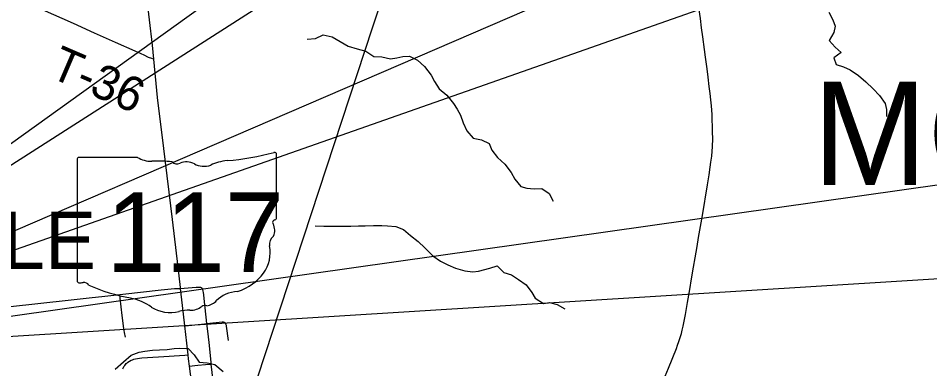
# Model space of a CAD drawing. Extents: x 0 to 34, y -5.4 to 22.
# Drawn here: x 5.887 to 7.394, y 17.496 to 18.075 of the extents above; entities that cross this region are included whole.
import ezdxf

# ---------------------------------------------------------------- set-up
doc = ezdxf.new("R2010")
doc.units = 0
for name, color, linetype in [('GM_X_City_Street', 7, 'Continuous'), ('GM_X_Corporation_Text', 7, 'Continuous'), ('GM_X_County_Road', 7, 'Continuous'), ('GM_X_Minor_River', 7, 'Continuous'), ('GM_X_Rail_Line', 7, 'Continuous'), ('GM_X_State_Location', 7, 'Continuous'), ('GM_X_State_Route', 7, 'Continuous'), ('GM_X_State_Shield', 7, 'Continuous'), ('GM_X_Township_Road', 7, 'Continuous'), ('GM_X_Township_Road_Text', 7, 'Continuous'), ('GM_X_Township_Text', 7, 'Continuous'), ('SH_Data', 7, 'Continuous')]:
    doc.layers.add(name, color=color, linetype=linetype)

msp = doc.modelspace()

# ---------------------------------------------------------------- linework, layer by layer
at = {"layer": 'GM_X_City_Street'}
for points in [[(6.1547, 17.6286), (6.1809, 17.6309), (6.184, 17.631), (6.1865, 17.6309), (6.188, 17.6308), (6.1893, 17.6304), (6.1901, 17.63), (6.1911, 17.6291)], [(6.2188, 17.3787), (6.2188, 17.3805), (6.2184, 17.3908), (6.218, 17.3978), (6.2177, 17.4025), (6.2162, 17.4177), (6.2132, 17.4434), (6.2093, 17.4763), (6.2061, 17.5038), (6.2057, 17.5073), (6.2023, 17.5396), (6.2002, 17.5585), (6.1989, 17.5707), (6.1943, 17.6123), (6.1937, 17.6185), (6.1932, 17.6219), (6.1927, 17.6245), (6.1921, 17.6269), (6.1911, 17.6291)], [(6.0645, 17.5485), (6.0626, 17.5561), (6.0614, 17.5624), (6.0587, 17.5839), (6.0554, 17.6128), (6.0547, 17.619)], [(6.1618, 17.5671), (6.1632, 17.5672), (6.1947, 17.5703), (6.1989, 17.5707), (6.2242, 17.5734), (6.2256, 17.5734), (6.2273, 17.5732), (6.2281, 17.5728), (6.2287, 17.5724), (6.2293, 17.5717), (6.2298, 17.5706), (6.2302, 17.5695), (6.2306, 17.5682), (6.2309, 17.5667), (6.234, 17.543)], [(6.0598, 17.4958), (6.0607, 17.498), (6.0618, 17.4997), (6.0631, 17.5017), (6.0643, 17.5033), (6.0654, 17.5047), (6.0669, 17.5059), (6.0684, 17.5072), (6.0709, 17.5089), (6.0738, 17.5102), (6.0758, 17.511), (6.0783, 17.512), (6.081, 17.5126), (6.084, 17.5133), (6.0874, 17.5137), (6.0913, 17.514), (6.1187, 17.5157), (6.1625, 17.5186), (6.1673, 17.5189)], [(6.1695, 17.5007), (6.1838, 17.502), (6.1965, 17.503), (6.2061, 17.5038)]]:
    msp.add_lwpolyline(points, dxfattribs=at)
at = {"layer": 'GM_X_County_Road'}
msp.add_lwpolyline([(6.956, 17.4841), (6.9615, 17.4973), (6.9747, 17.5295), (6.9768, 17.5351), (6.9791, 17.5412), (6.9811, 17.5476), (6.9831, 17.5543), (6.9846, 17.56), (6.9861, 17.5664), (6.9877, 17.5745), (6.9899, 17.5859), (6.9933, 17.6056), (6.9964, 17.6239), (7.0004, 17.6477), (7.0031, 17.6638), (7.0058, 17.6796), (7.009, 17.6979), (7.0115, 17.7127), (7.0156, 17.7371), (7.0177, 17.7494), (7.0261, 17.7997), (7.0288, 17.8162), (7.0308, 17.8292), (7.0318, 17.8372), (7.0331, 17.8471), (7.0345, 17.8632), (7.0349, 17.8757), (7.0347, 17.8875), (7.0345, 17.8968), (7.0341, 17.9069), (7.0338, 17.9161), (7.0327, 17.9304), (7.0316, 17.9403), (7.0305, 17.9505), (7.0291, 17.9625), (7.0273, 17.9778), (7.0256, 17.9915), (7.023, 18.0105), (7.0213, 18.0235), (7.0184, 18.0445), (7.0165, 18.0591), (7.0144, 18.0746), (7.012, 18.0925)], dxfattribs=at)
at = {"layer": 'GM_X_Minor_River'}
for points in [[(7.2265, 18.0851), (7.2335, 18.0724), (7.2371, 18.0621), (7.235, 18.0512), (7.2272, 18.038), (7.2372, 18.0272), (7.2469, 18.0183), (7.2351, 18.0094), (7.2387, 17.9984), (7.2511, 17.9947), (7.262, 17.99), (7.2758, 17.9807), (7.2881, 17.9698), (7.3001, 17.9586), (7.3105, 17.9474), (7.3197, 17.9344), (7.3222, 17.9245), (7.322, 17.9127)], [(6.3648, 18.0404), (6.3781, 18.0417), (6.3911, 18.0476), (6.4058, 18.0443), (6.4189, 18.0368), (6.4324, 18.0287), (6.4474, 18.0246), (6.4614, 18.0206), (6.4749, 18.012), (6.4881, 18.0114), (6.502, 18.0081), (6.513, 18.0095), (6.5225, 18.0116), (6.5339, 18.0121), (6.5467, 18.0055), (6.5586, 17.9954), (6.5697, 17.9808), (6.5748, 17.9705), (6.5826, 17.9586), (6.5953, 17.9481), (6.6064, 17.9343), (6.6123, 17.9247), (6.6178, 17.9147), (6.6225, 17.9021), (6.6284, 17.8891), (6.6388, 17.8772), (6.6527, 17.8743), (6.6651, 17.868), (6.6695, 17.8569), (6.6791, 17.845), (6.6914, 17.8338), (6.7018, 17.8204), (6.708, 17.8092), (6.7177, 17.7973), (6.7278, 17.7941), (6.7395, 17.7935), (6.7524, 17.7937), (6.7644, 17.7855), (6.771, 17.7729)], [(6.3775, 17.7321), (6.3919, 17.7315), (6.4059, 17.7316), (6.4203, 17.7314), (6.4365, 17.7315), (6.4494, 17.732), (6.4604, 17.7322), (6.4744, 17.7327), (6.4877, 17.7329), (6.4975, 17.7323), (6.5111, 17.731), (6.5239, 17.7262), (6.5354, 17.7161), (6.5478, 17.7064), (6.559, 17.696), (6.572, 17.6829), (6.5847, 17.6736), (6.5971, 17.668), (6.6099, 17.6625), (6.6249, 17.6577), (6.6381, 17.6564), (6.6476, 17.6573), (6.6666, 17.6623), (6.6788, 17.6663), (6.6896, 17.6551), (6.7024, 17.6515), (6.714, 17.6437), (6.7263, 17.6348), (6.736, 17.6221), (6.7415, 17.6125), (6.7553, 17.6039), (6.7652, 17.6056), (6.778, 17.602), (6.7904, 17.5953)], [(6.0474, 17.4955), (6.0609, 17.5078), (6.0735, 17.5186), (6.0869, 17.5233), (6.0964, 17.5254), (6.1089, 17.5268), (6.1202, 17.5273), (6.1331, 17.5279), (6.1449, 17.5296), (6.1543, 17.5302), (6.1676, 17.5296), (6.1776, 17.5191), (6.1861, 17.5072), (6.1994, 17.5059), (6.2118, 17.503), (6.2256, 17.4918)]]:
    msp.add_lwpolyline(points, dxfattribs=at)
at = {"layer": 'GM_X_Rail_Line'}
msp.add_lwpolyline([(8.2982, 20.9), (7.9149, 20.4347), (7.2657, 19.6601), (6.962, 19.2874), (6.9019, 19.2104), (6.8655, 19.1557), (6.8321, 19.1035), (6.789, 19.0121), (6.7581, 18.9233), (6.7239, 18.8129), (6.4727, 18.0601), (6.244, 17.3648), (6.1298, 17.0307)], dxfattribs=at)
at = {"layer": 'GM_X_State_Route'}
for p, q in [((6.1545, 17.6306), (6.1547, 17.6286)), ((6.0044, 17.6133), (6.0303, 17.6162))]:
    msp.add_line(p, q, dxfattribs=at)
for points in [[(6.0388, 18.589), (6.0431, 18.5659), (6.0463, 18.5467), (6.049, 18.5279), (6.0672, 18.3786), (6.0826, 18.2509), (6.0912, 18.1762), (6.0987, 18.1145), (6.1083, 18.0305), (6.1106, 18.0074), (6.1167, 17.9439), (6.1271, 17.8601), (6.1412, 17.7428), (6.151, 17.6639), (6.1545, 17.6306)], [(6.0303, 17.6162), (6.0547, 17.619), (6.06, 17.6196), (6.1231, 17.6266), (6.1455, 17.6286), (6.1495, 17.6288), (6.1524, 17.6287), (6.1547, 17.6286)], [(6.1547, 17.6286), (6.158, 17.6004), (6.1618, 17.5671)], [(4.9955, 17.5005), (5.1865, 17.5218), (5.3451, 17.5394), (5.4298, 17.5482), (5.4404, 17.5493), (5.5298, 17.56), (5.6607, 17.5749), (5.7984, 17.5904), (5.8742, 17.5989), (5.9694, 17.6094), (6.0044, 17.6133)], [(6.1618, 17.5671), (6.1651, 17.5384), (6.1673, 17.5189)], [(6.1673, 17.5189), (6.1681, 17.5127), (6.1695, 17.5007)], [(6.1695, 17.5007), (6.1726, 17.4749), (6.1766, 17.4402)]]:
    msp.add_lwpolyline(points, dxfattribs=at)
at = {"layer": 'GM_X_State_Shield'}
for p, q in [((5.9843, 17.8417), (5.9843, 17.6416)), ((6.0841, 17.8452), (5.9875, 17.8452)), ((6.3139, 17.7455), (6.3139, 17.8501)), ((6.3138, 17.7455), (6.3139, 17.7455))]:
    msp.add_line(p, q, dxfattribs=at)
for centre, major_axis, start_param, end_param in [((6.1965, 18.118), (0.3495, 0), 4.814394, 5.042369), ((6.3102, 17.8506), (0.00367, 0), 6.141152, 7.989035), ((5.9881, 17.8422), (0.00382, 0), 1.712693, 3.28349), ((6.107, 17.8684), (0.037, 0), 4.042523, 4.731795), ((6.1193, 17.7328), (0.133, 0), 1.404758, 1.657858), ((6.1652, 17.8201), (0.0222, 0), 0.950623, 2.079405), ((6.2411, 17.7841), (0.0703, 0), 1.699011, 2.107814), ((6.1495, 17.8432), (0.0107, 0), 3.836095, 5.185415), ((6.1939, 17.8518), (0.0267, 0), 4.081561, 5.145723), ((6.313, 17.7378), (0.00568, 0), 1.883978, 3.671073), ((6.2769, 17.7245), (0.0341, 0), 5.934695, 6.695948), ((6.31, 17.7451), (0.00393, 0), 5.05454, 6.418171), ((6.327, 17.7016), (0.0248, 0), 2.387724, 3.262537), ((6.2161, 17.6883), (0.0874, 0), 5.101752, 6.440018), ((5.9881, 17.6412), (0.00385, 0), 3.00124, 4.508301), ((5.9887, 17.6617), (0.0294, 0), 4.665946, 4.897461), ((5.9947, 17.6301), (0.0106, 0), 0.519207, 1.627899), ((6.1285, 17.8099), (0.2524, 0), 4.195997, 4.488961), ((6.0533, 17.5517), (0.079, 0), 0.823519, 1.323587), ((6.2529, 17.5854), (0.0479, 0), 1.647645, 2.488434), ((6.1387, 17.6291), (0.0501, 0), 4.026481, 4.996735), ((6.1713, 17.6141), (0.0267, 0), 4.691044, 5.507374), ((6.1955, 17.5947), (0.00752, 0), 1.147584, 2.315152), ((6.1923, 17.6222), (0.0282, 0), 4.937069, 5.64225), ((6.1676, 17.5599), (0.0412, 0), 1.495662, 1.94098)]:
    msp.add_ellipse(centre, major_axis=major_axis, ratio=0.8, start_param=start_param, end_param=end_param, dxfattribs=at)
at = {"layer": 'GM_X_Township_Road'}
msp.add_lwpolyline([(6.1106, 18.0074), (6.1077, 18.0085), (6.1023, 18.0104), (6.0949, 18.0138), (6.0803, 18.0206), (6.0478, 18.0348), (6.0133, 18.0504), (5.9781, 18.0662), (5.9271, 18.089)], dxfattribs=at)
at = {"layer": 'SH_Data'}
for points in [[(9.2327, 20.2782), (5.4298, 17.5482), (9.2327, 19.9788)], [(9.2327, 19.1682), (5.4895, 17.5552), (9.2327, 18.8687)], [(9.2327, 18.0581), (5.4613, 17.524), (9.2327, 17.7586)]]:
    msp.add_lwpolyline(points, close=True, dxfattribs=at)

# ---------------------------------------------------------------- texts
at = {"layer": 'GM_X_Corporation_Text'}
msp.add_text('HUNTSVILLE', height=0.0947, rotation=0, dxfattribs=at).set_placement((5.2345, 17.6609))
at = {"layer": 'GM_X_State_Location'}
for s in ['s', 'r']:
    msp.add_text(s, height=0.000189, dxfattribs=at).set_placement((6.1454, 17.7284))
msp.add_text('117', height=0.000189, rotation=0, dxfattribs=at).set_placement((6.0785, 17.7146))
at = {"layer": 'GM_X_State_Shield'}
msp.add_text('117', height=0.13184, dxfattribs=at).set_placement((6.0322, 17.6557))
at = {"layer": 'GM_X_Township_Road_Text'}
msp.add_text('T-36', height=0.05682, rotation=336.7538, dxfattribs=at).set_placement((5.9363, 17.9787))
at = {"layer": 'GM_X_Township_Text'}
msp.add_text('MCARTHUR', height=0.17045, rotation=0, dxfattribs=at).set_placement((7.1998, 17.7998))

doc.saveas('drawing.dxf')
